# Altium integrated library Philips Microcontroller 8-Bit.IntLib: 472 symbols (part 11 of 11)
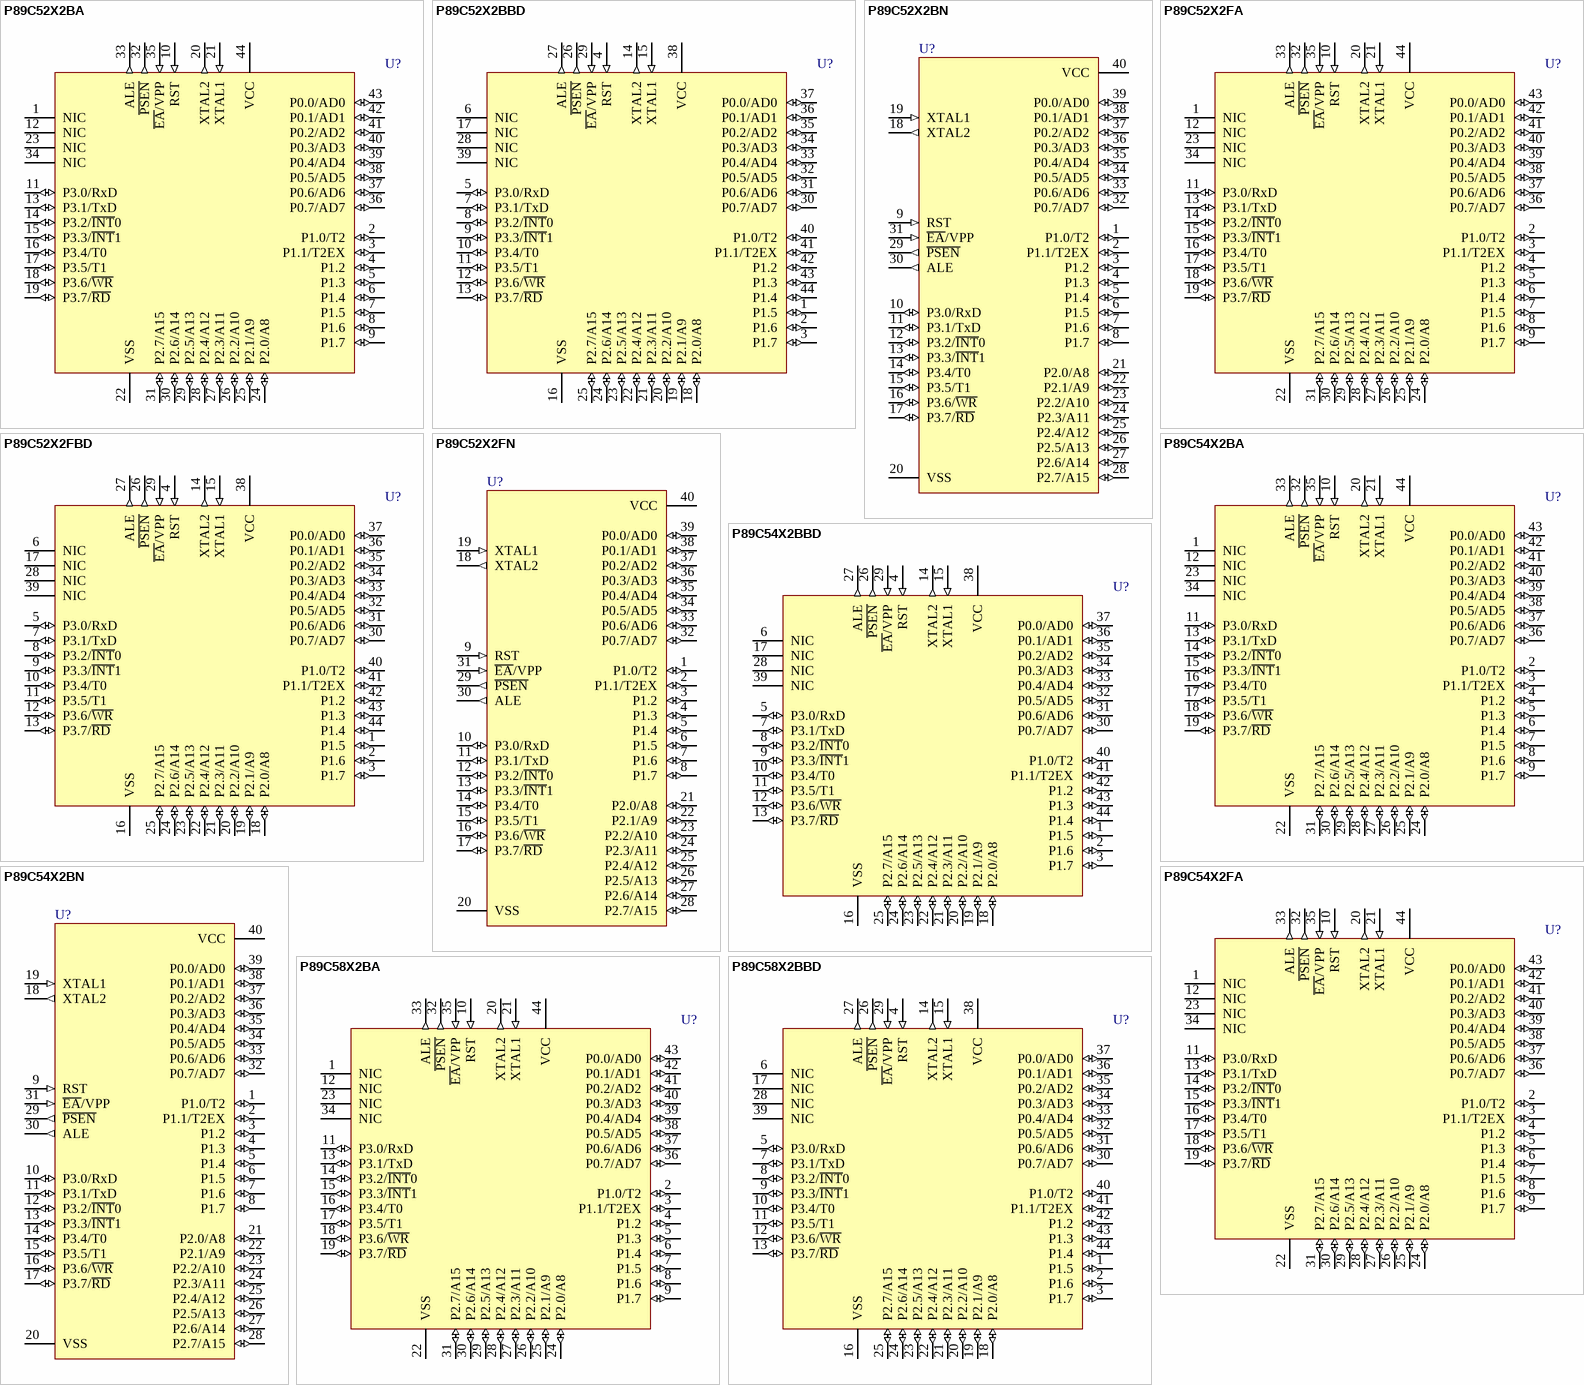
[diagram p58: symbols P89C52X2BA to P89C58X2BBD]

## P89C54X2BBD
designator U?
80C51 8-Bit Flash Microcontroller Family, 16 kB Flash
footprint SOT389-1_N (Thin QFP, 44-Leads, Body 10x10mm, Pitch 0.8mm, IPC Medium Density)
footprint SOT389-1_L (Thin QFP, 44-Leads, Body 10x10mm, Pitch 0.8mm, IPC High Density)
footprint SOT389-1_M (Thin QFP, 44-Leads, Body 10x10mm, Pitch 0.8mm, IPC Low Density)
pins: 1 P1.5 (io), 2 P1.6 (io), 3 P1.7 (io), 4 RST (in), 5 P3.0/RxD (io), 6 NIC, 7 P3.1/TxD (io), 8 P3.2/~{INT}0 (io), 9 P3.3/~{INT}1 (io), 10 P3.4/T0 (io), 11 P3.5/T1 (io), 12 P3.6/~{WR} (io), 13 P3.7/~{RD} (io), 14 XTAL2 (out), 15 XTAL1 (in), 16 VSS (power), 17 NIC, 18 P2.0/A8 (io), 19 P2.1/A9 (io), 20 P2.2/A10 (io), 21 P2.3/A11 (io), 22 P2.4/A12 (io), 23 P2.5/A13 (io), 24 P2.6/A14 (io), 25 P2.7/A15 (io), 26 ~{PSEN} (out), 27 ALE (out), 28 NIC, 29 ~{EA}/VPP (in), 30 P0.7/AD7 (io), 31 P0.6/AD6 (io), 32 P0.5/AD5 (io), 33 P0.4/AD4 (io), 34 P0.3/AD3 (io), 35 P0.2/AD2 (io), 36 P0.1/AD1 (io), 37 P0.0/AD0 (io), 38 VCC (power), 39 NIC, 40 P1.0/T2 (io), 41 P1.1/T2EX (io), 42 P1.2 (io), 43 P1.3 (io), 44 P1.4 (io)

## P89C54X2BN
designator U?
80C51 8-Bit Flash Microcontroller Family, 16 kB Flash
footprint SOT129-1 (DIP, Plastic; 40 Leads; Row Spacing 15.24 mm; Pitch 2.54 mm)
pins: 1 P1.0/T2 (io), 2 P1.1/T2EX (io), 3 P1.2 (io), 4 P1.3 (io), 5 P1.4 (io), 6 P1.5 (io), 7 P1.6 (io), 8 P1.7 (io), 9 RST (in), 10 P3.0/RxD (io), 11 P3.1/TxD (io), 12 P3.2/~{INT}0 (io), 13 P3.3/~{INT}1 (io), 14 P3.4/T0 (io), 15 P3.5/T1 (io), 16 P3.6/~{WR} (io), 17 P3.7/~{RD} (io), 18 XTAL2 (out), 19 XTAL1 (in), 20 VSS (power), 21 P2.0/A8 (io), 22 P2.1/A9 (io), 23 P2.2/A10 (io), 24 P2.3/A11 (io), 25 P2.4/A12 (io), 26 P2.5/A13 (io), 27 P2.6/A14 (io), 28 P2.7/A15 (io), 29 ~{PSEN} (out), 30 ALE (out), 31 ~{EA}/VPP (in), 32 P0.7/AD7 (io), 33 P0.6/AD6 (io), 34 P0.5/AD5 (io), 35 P0.4/AD4 (io), 36 P0.3/AD3 (io), 37 P0.2/AD2 (io), 38 P0.1/AD1 (io), 39 P0.0/AD0 (io), 40 VCC (power)

## P89C54X2FA
designator U?
80C51 8-Bit Flash Microcontroller Family, 16 kB Flash
footprint SOT187-2_N (Leaded Chip Carrier, 44-Leads, Body 16.6x16.6mm, Pitch 1.27mm, IPC Medium Density)
footprint SOT187-2_L (Leaded Chip Carrier, 44-Leads, Body 16.6x16.6mm, Pitch 1.27mm, IPC High Density)
footprint SOT187-2_M (Leaded Chip Carrier, 44-Leads, Body 16.6x16.6mm, Pitch 1.27mm, IPC Low Density)
pins: 1 NIC, 2 P1.0/T2 (io), 3 P1.1/T2EX (io), 4 P1.2 (io), 5 P1.3 (io), 6 P1.4 (io), 7 P1.5 (io), 8 P1.6 (io), 9 P1.7 (io), 10 RST (in), 11 P3.0/RxD (io), 12 NIC, 13 P3.1/TxD (io), 14 P3.2/~{INT}0 (io), 15 P3.3/~{INT}1 (io), 16 P3.4/T0 (io), 17 P3.5/T1 (io), 18 P3.6/~{WR} (io), 19 P3.7/~{RD} (io), 20 XTAL2 (out), 21 XTAL1 (in), 22 VSS (power), 23 NIC, 24 P2.0/A8 (io), 25 P2.1/A9 (io), 26 P2.2/A10 (io), 27 P2.3/A11 (io), 28 P2.4/A12 (io), 29 P2.5/A13 (io), 30 P2.6/A14 (io), 31 P2.7/A15 (io), 32 ~{PSEN} (out), 33 ALE (out), 34 NIC, 35 ~{EA}/VPP (in), 36 P0.7/AD7 (io), 37 P0.6/AD6 (io), 38 P0.5/AD5 (io), 39 P0.4/AD4 (io), 40 P0.3/AD3 (io), 41 P0.2/AD2 (io), 42 P0.1/AD1 (io), 43 P0.0/AD0 (io), 44 VCC (power)

## P89C58X2BA
designator U?
80C51 8-Bit Flash Microcontroller Family, 32 kB Flash
footprint SOT187-2_N (Leaded Chip Carrier, 44-Leads, Body 16.6x16.6mm, Pitch 1.27mm, IPC Medium Density)
footprint SOT187-2_L (Leaded Chip Carrier, 44-Leads, Body 16.6x16.6mm, Pitch 1.27mm, IPC High Density)
footprint SOT187-2_M (Leaded Chip Carrier, 44-Leads, Body 16.6x16.6mm, Pitch 1.27mm, IPC Low Density)
pins: 1 NIC, 2 P1.0/T2 (io), 3 P1.1/T2EX (io), 4 P1.2 (io), 5 P1.3 (io), 6 P1.4 (io), 7 P1.5 (io), 8 P1.6 (io), 9 P1.7 (io), 10 RST (in), 11 P3.0/RxD (io), 12 NIC, 13 P3.1/TxD (io), 14 P3.2/~{INT}0 (io), 15 P3.3/~{INT}1 (io), 16 P3.4/T0 (io), 17 P3.5/T1 (io), 18 P3.6/~{WR} (io), 19 P3.7/~{RD} (io), 20 XTAL2 (out), 21 XTAL1 (in), 22 VSS (power), 23 NIC, 24 P2.0/A8 (io), 25 P2.1/A9 (io), 26 P2.2/A10 (io), 27 P2.3/A11 (io), 28 P2.4/A12 (io), 29 P2.5/A13 (io), 30 P2.6/A14 (io), 31 P2.7/A15 (io), 32 ~{PSEN} (out), 33 ALE (out), 34 NIC, 35 ~{EA}/VPP (in), 36 P0.7/AD7 (io), 37 P0.6/AD6 (io), 38 P0.5/AD5 (io), 39 P0.4/AD4 (io), 40 P0.3/AD3 (io), 41 P0.2/AD2 (io), 42 P0.1/AD1 (io), 43 P0.0/AD0 (io), 44 VCC (power)

## P89C58X2BBD
designator U?
80C51 8-Bit Flash Microcontroller Family, 32 kB Flash
footprint SOT389-1_N (Thin QFP, 44-Leads, Body 10x10mm, Pitch 0.8mm, IPC Medium Density)
footprint SOT389-1_L (Thin QFP, 44-Leads, Body 10x10mm, Pitch 0.8mm, IPC High Density)
footprint SOT389-1_M (Thin QFP, 44-Leads, Body 10x10mm, Pitch 0.8mm, IPC Low Density)
pins: 1 P1.5 (io), 2 P1.6 (io), 3 P1.7 (io), 4 RST (in), 5 P3.0/RxD (io), 6 NIC, 7 P3.1/TxD (io), 8 P3.2/~{INT}0 (io), 9 P3.3/~{INT}1 (io), 10 P3.4/T0 (io), 11 P3.5/T1 (io), 12 P3.6/~{WR} (io), 13 P3.7/~{RD} (io), 14 XTAL2 (out), 15 XTAL1 (in), 16 VSS (power), 17 NIC, 18 P2.0/A8 (io), 19 P2.1/A9 (io), 20 P2.2/A10 (io), 21 P2.3/A11 (io), 22 P2.4/A12 (io), 23 P2.5/A13 (io), 24 P2.6/A14 (io), 25 P2.7/A15 (io), 26 ~{PSEN} (out), 27 ALE (out), 28 NIC, 29 ~{EA}/VPP (in), 30 P0.7/AD7 (io), 31 P0.6/AD6 (io), 32 P0.5/AD5 (io), 33 P0.4/AD4 (io), 34 P0.3/AD3 (io), 35 P0.2/AD2 (io), 36 P0.1/AD1 (io), 37 P0.0/AD0 (io), 38 VCC (power), 39 NIC, 40 P1.0/T2 (io), 41 P1.1/T2EX (io), 42 P1.2 (io), 43 P1.3 (io), 44 P1.4 (io)

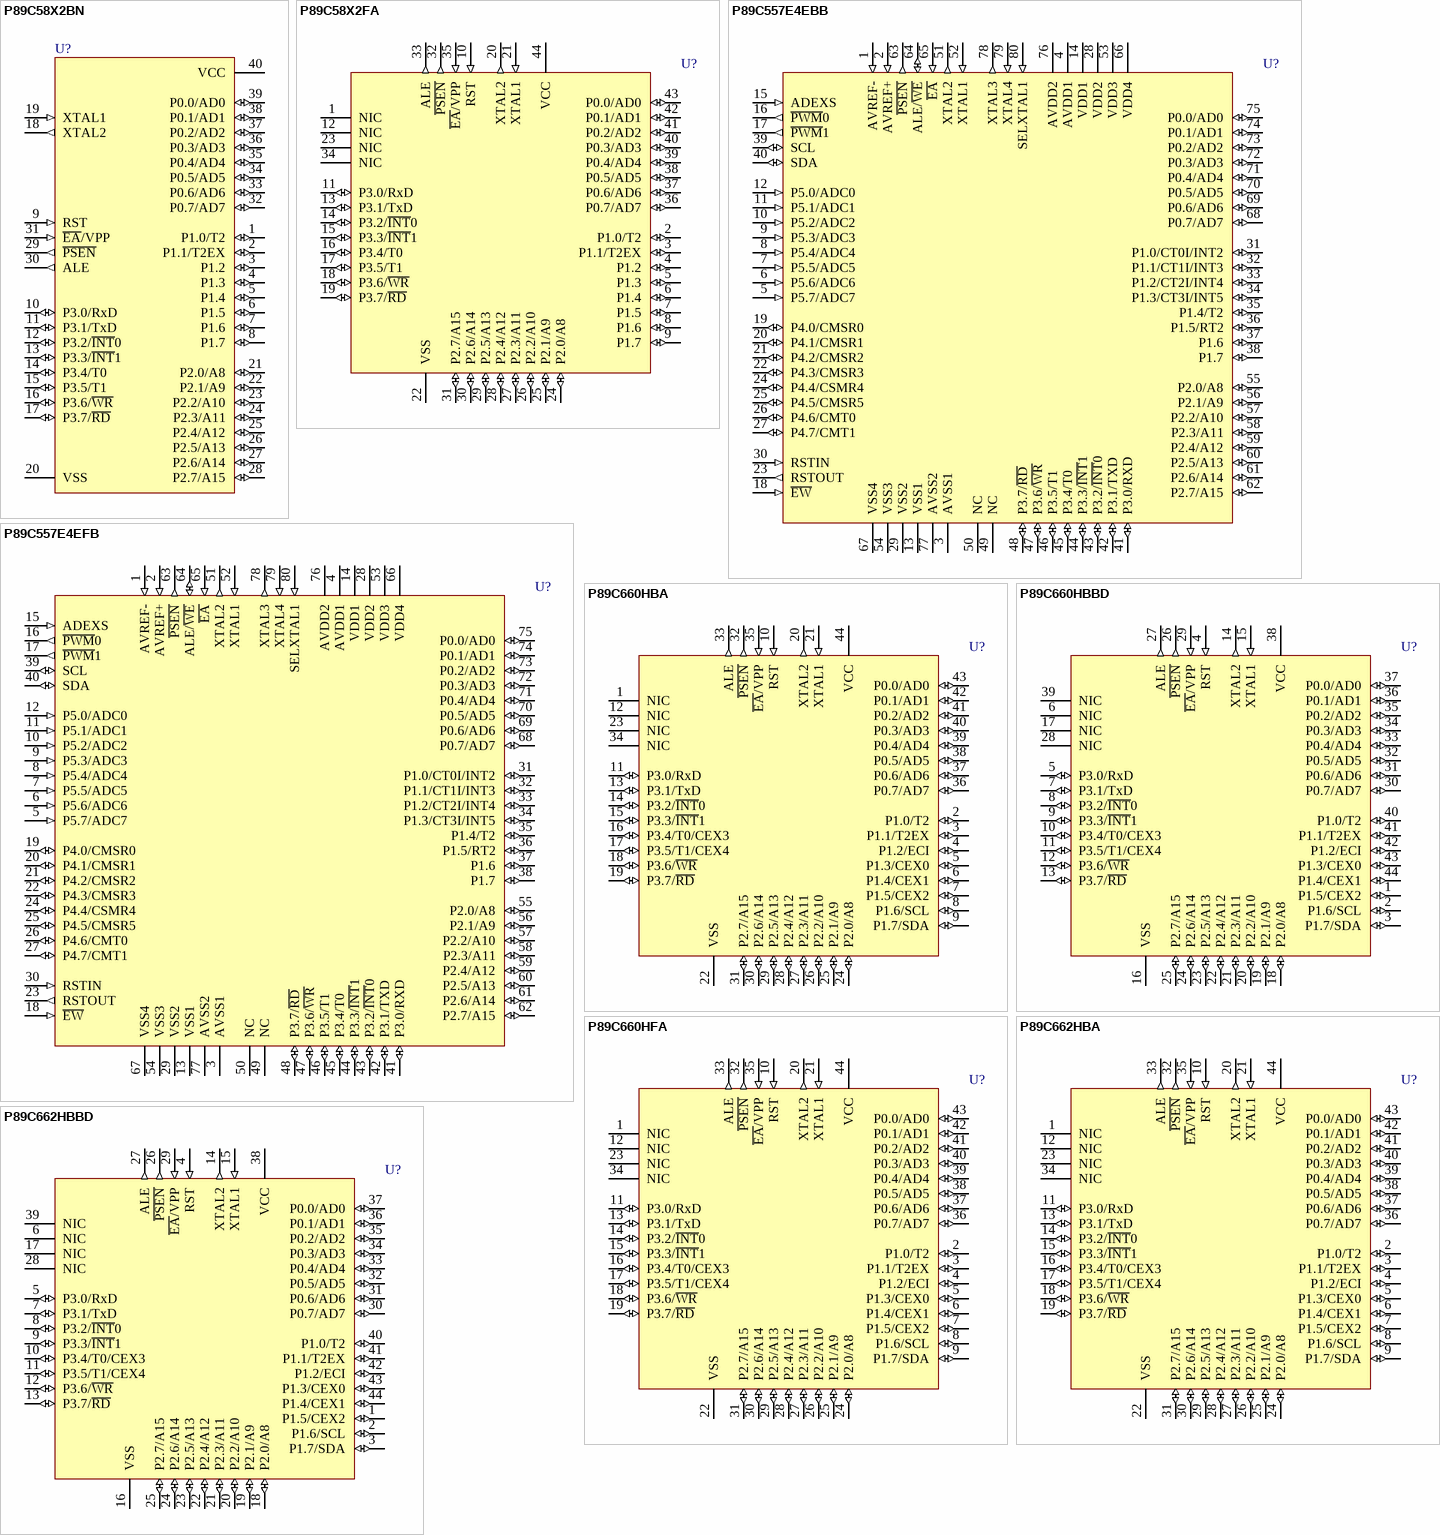
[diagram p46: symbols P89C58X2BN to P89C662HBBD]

## P89C58X2BN
designator U?
80C51 8-Bit Flash Microcontroller Family, 32 kB Flash
footprint SOT129-1 (DIP, Plastic; 40 Leads; Row Spacing 15.24 mm; Pitch 2.54 mm)
pins: 1 P1.0/T2 (io), 2 P1.1/T2EX (io), 3 P1.2 (io), 4 P1.3 (io), 5 P1.4 (io), 6 P1.5 (io), 7 P1.6 (io), 8 P1.7 (io), 9 RST (in), 10 P3.0/RxD (io), 11 P3.1/TxD (io), 12 P3.2/~{INT}0 (io), 13 P3.3/~{INT}1 (io), 14 P3.4/T0 (io), 15 P3.5/T1 (io), 16 P3.6/~{WR} (io), 17 P3.7/~{RD} (io), 18 XTAL2 (out), 19 XTAL1 (in), 20 VSS (power), 21 P2.0/A8 (io), 22 P2.1/A9 (io), 23 P2.2/A10 (io), 24 P2.3/A11 (io), 25 P2.4/A12 (io), 26 P2.5/A13 (io), 27 P2.6/A14 (io), 28 P2.7/A15 (io), 29 ~{PSEN} (out), 30 ALE (out), 31 ~{EA}/VPP (in), 32 P0.7/AD7 (io), 33 P0.6/AD6 (io), 34 P0.5/AD5 (io), 35 P0.4/AD4 (io), 36 P0.3/AD3 (io), 37 P0.2/AD2 (io), 38 P0.1/AD1 (io), 39 P0.0/AD0 (io), 40 VCC (power)

## P89C58X2FA
designator U?
80C51 8-Bit Flash Microcontroller Family, 32 kB Flash
footprint SOT187-2_N (Leaded Chip Carrier, 44-Leads, Body 16.6x16.6mm, Pitch 1.27mm, IPC Medium Density)
footprint SOT187-2_L (Leaded Chip Carrier, 44-Leads, Body 16.6x16.6mm, Pitch 1.27mm, IPC High Density)
footprint SOT187-2_M (Leaded Chip Carrier, 44-Leads, Body 16.6x16.6mm, Pitch 1.27mm, IPC Low Density)
pins: 1 NIC, 2 P1.0/T2 (io), 3 P1.1/T2EX (io), 4 P1.2 (io), 5 P1.3 (io), 6 P1.4 (io), 7 P1.5 (io), 8 P1.6 (io), 9 P1.7 (io), 10 RST (in), 11 P3.0/RxD (io), 12 NIC, 13 P3.1/TxD (io), 14 P3.2/~{INT}0 (io), 15 P3.3/~{INT}1 (io), 16 P3.4/T0 (io), 17 P3.5/T1 (io), 18 P3.6/~{WR} (io), 19 P3.7/~{RD} (io), 20 XTAL2 (out), 21 XTAL1 (in), 22 VSS (power), 23 NIC, 24 P2.0/A8 (io), 25 P2.1/A9 (io), 26 P2.2/A10 (io), 27 P2.3/A11 (io), 28 P2.4/A12 (io), 29 P2.5/A13 (io), 30 P2.6/A14 (io), 31 P2.7/A15 (io), 32 ~{PSEN} (out), 33 ALE (out), 34 NIC, 35 ~{EA}/VPP (in), 36 P0.7/AD7 (io), 37 P0.6/AD6 (io), 38 P0.5/AD5 (io), 39 P0.4/AD4 (io), 40 P0.3/AD3 (io), 41 P0.2/AD2 (io), 42 P0.1/AD1 (io), 43 P0.0/AD0 (io), 44 VCC (power)

## P89C557E4EBB
designator U?
Single-Chip 8-Bit Microcontroller, FEEPROM Type
footprint SOT318-1_N (QFP, 80-Leads, Body 20x14mm, Pitch 0.8mm, IPC Medium Density)
footprint SOT318-1_L (QFP, 80-Leads, Body 20x14mm, Pitch 0.8mm, IPC High Density)
footprint SOT318-1_M (QFP, 80-Leads, Body 20x14mm, Pitch 0.8mm, IPC Low Density)
pins: 1 AVREF- (in), 2 AVREF+ (in), 3 AVSS1 (power), 4 AVDD1 (power), 5 P5.7/ADC7 (in), 6 P5.6/ADC6 (in), 7 P5.5/ADC5 (in), 8 P5.4/ADC4 (in), 9 P5.3/ADC3 (in), 10 P5.2/ADC2 (in), 11 P5.1/ADC1 (in), 12 P5.0/ADC0 (in), 13 VSS1 (power), 14 VDD1 (power), 15 ADEXS (in), 16 ~{PWM}0 (out), 17 ~{PWM}1 (out), 18 ~{EW} (in), 19 P4.0/CMSR0 (io), 20 P4.1/CMSR1 (io), 21 P4.2/CMSR2 (io), 22 P4.3/CMSR3 (io), 23 RSTOUT (out), 24 P4.4/CSMR4 (io), 25 P4.5/CMSR5 (io), 26 P4.6/CMT0 (io), 27 P4.7/CMT1 (io), 28 VDD2 (power), 29 VSS2 (power), 30 RSTIN (in), 31 P1.0/CT0I/INT2 (io), 32 P1.1/CT1I/INT3 (io), 33 P1.2/CT2I/INT4 (io), 34 P1.3/CT3I/INT5 (io), 35 P1.4/T2 (io), 36 P1.5/RT2 (io), 37 P1.6 (io), 38 P1.7 (io), 39 SCL (io), 40 SDA (io), 41 P3.0/RXD (io), 42 P3.1/TXD (io), 43 P3.2/~{INT}0 (io), 44 P3.3/~{INT}1 (io), 45 P3.4/T0 (io), 46 P3.5/T1 (io), 47 P3.6/~{WR} (io), 48 P3.7/~{RD} (io), 49 NC, 50 NC, 51 XTAL2 (out), 52 XTAL1 (in), 53 VDD3 (power), 54 VSS3 (power), 55 P2.0/A8 (io), 56 P2.1/A9 (io), 57 P2.2/A10 (io), 58 P2.3/A11 (io), 59 P2.4/A12 (io), 60 P2.5/A13 (io), 61 P2.6/A14 (io), 62 P2.7/A15 (io), 63 ~{PSEN} (out), 64 ALE/~{WE} (io), 65 ~{EA} (in), 66 VDD4 (power), 67 VSS4 (power), 68 P0.7/AD7 (io), 69 P0.6/AD6 (io), 70 P0.5/AD5 (io), 71 P0.4/AD4 (io), 72 P0.3/AD3 (io), 73 P0.2/AD2 (io), 74 P0.1/AD1 (io), 75 P0.0/AD0 (io), 76 AVDD2 (power), 77 AVSS2 (power), 78 XTAL3 (out), 79 XTAL4 (in), 80 SELXTAL1 (in)

## P89C557E4EFB
designator U?
Single-Chip 8-Bit Microcontroller, FEEPROM Type
footprint SOT318-1_N (QFP, 80-Leads, Body 20x14mm, Pitch 0.8mm, IPC Medium Density)
footprint SOT318-1_L (QFP, 80-Leads, Body 20x14mm, Pitch 0.8mm, IPC High Density)
footprint SOT318-1_M (QFP, 80-Leads, Body 20x14mm, Pitch 0.8mm, IPC Low Density)
pins: 1 AVREF- (in), 2 AVREF+ (in), 3 AVSS1 (power), 4 AVDD1 (power), 5 P5.7/ADC7 (in), 6 P5.6/ADC6 (in), 7 P5.5/ADC5 (in), 8 P5.4/ADC4 (in), 9 P5.3/ADC3 (in), 10 P5.2/ADC2 (in), 11 P5.1/ADC1 (in), 12 P5.0/ADC0 (in), 13 VSS1 (power), 14 VDD1 (power), 15 ADEXS (in), 16 ~{PWM}0 (out), 17 ~{PWM}1 (out), 18 ~{EW} (in), 19 P4.0/CMSR0 (io), 20 P4.1/CMSR1 (io), 21 P4.2/CMSR2 (io), 22 P4.3/CMSR3 (io), 23 RSTOUT (out), 24 P4.4/CSMR4 (io), 25 P4.5/CMSR5 (io), 26 P4.6/CMT0 (io), 27 P4.7/CMT1 (io), 28 VDD2 (power), 29 VSS2 (power), 30 RSTIN (in), 31 P1.0/CT0I/INT2 (io), 32 P1.1/CT1I/INT3 (io), 33 P1.2/CT2I/INT4 (io), 34 P1.3/CT3I/INT5 (io), 35 P1.4/T2 (io), 36 P1.5/RT2 (io), 37 P1.6 (io), 38 P1.7 (io), 39 SCL (io), 40 SDA (io), 41 P3.0/RXD (io), 42 P3.1/TXD (io), 43 P3.2/~{INT}0 (io), 44 P3.3/~{INT}1 (io), 45 P3.4/T0 (io), 46 P3.5/T1 (io), 47 P3.6/~{WR} (io), 48 P3.7/~{RD} (io), 49 NC, 50 NC, 51 XTAL2 (out), 52 XTAL1 (in), 53 VDD3 (power), 54 VSS3 (power), 55 P2.0/A8 (io), 56 P2.1/A9 (io), 57 P2.2/A10 (io), 58 P2.3/A11 (io), 59 P2.4/A12 (io), 60 P2.5/A13 (io), 61 P2.6/A14 (io), 62 P2.7/A15 (io), 63 ~{PSEN} (out), 64 ALE/~{WE} (io), 65 ~{EA} (in), 66 VDD4 (power), 67 VSS4 (power), 68 P0.7/AD7 (io), 69 P0.6/AD6 (io), 70 P0.5/AD5 (io), 71 P0.4/AD4 (io), 72 P0.3/AD3 (io), 73 P0.2/AD2 (io), 74 P0.1/AD1 (io), 75 P0.0/AD0 (io), 76 AVDD2 (power), 77 AVSS2 (power), 78 XTAL3 (out), 79 XTAL4 (in), 80 SELXTAL1 (in)

## P89C660HBA
designator U?
80C51 8-Bit Flash Microcontroller Family, 16 kB ISP/IAP Flash with 512 B RAM
footprint SOT187-2_N (Leaded Chip Carrier, 44-Leads, Body 16.6x16.6mm, Pitch 1.27mm, IPC Medium Density)
footprint SOT187-2_L (Leaded Chip Carrier, 44-Leads, Body 16.6x16.6mm, Pitch 1.27mm, IPC High Density)
footprint SOT187-2_M (Leaded Chip Carrier, 44-Leads, Body 16.6x16.6mm, Pitch 1.27mm, IPC Low Density)
pins: 1 NIC, 2 P1.0/T2 (io), 3 P1.1/T2EX (io), 4 P1.2/ECI (io), 5 P1.3/CEX0 (io), 6 P1.4/CEX1 (io), 7 P1.5/CEX2 (io), 8 P1.6/SCL (io), 9 P1.7/SDA (io), 10 RST (in), 11 P3.0/RxD (io), 12 NIC, 13 P3.1/TxD (io), 14 P3.2/~{INT}0 (io), 15 P3.3/~{INT}1 (io), 16 P3.4/T0/CEX3 (io), 17 P3.5/T1/CEX4 (io), 18 P3.6/~{WR} (io), 19 P3.7/~{RD} (io), 20 XTAL2 (out), 21 XTAL1 (in), 22 VSS (power), 23 NIC, 24 P2.0/A8 (io), 25 P2.1/A9 (io), 26 P2.2/A10 (io), 27 P2.3/A11 (io), 28 P2.4/A12 (io), 29 P2.5/A13 (io), 30 P2.6/A14 (io), 31 P2.7/A15 (io), 32 ~{PSEN} (out), 33 ALE (out), 34 NIC, 35 ~{EA}/VPP (in), 36 P0.7/AD7 (io), 37 P0.6/AD6 (io), 38 P0.5/AD5 (io), 39 P0.4/AD4 (io), 40 P0.3/AD3 (io), 41 P0.2/AD2 (io), 42 P0.1/AD1 (io), 43 P0.0/AD0 (io), 44 VCC (power)

## P89C660HBBD
designator U?
80C51 8-Bit Flash Microcontroller Family, 16 kB ISP/IAP Flash with 512 B RAM
footprint SOT389-1_N (Thin QFP, 44-Leads, Body 10x10mm, Pitch 0.8mm, IPC Medium Density)
footprint SOT389-1_L (Thin QFP, 44-Leads, Body 10x10mm, Pitch 0.8mm, IPC High Density)
footprint SOT389-1_M (Thin QFP, 44-Leads, Body 10x10mm, Pitch 0.8mm, IPC Low Density)
pins: 1 P1.5/CEX2 (io), 2 P1.6/SCL (io), 3 P1.7/SDA (io), 4 RST (in), 5 P3.0/RxD (io), 6 NIC, 7 P3.1/TxD (io), 8 P3.2/~{INT}0 (io), 9 P3.3/~{INT}1 (io), 10 P3.4/T0/CEX3 (io), 11 P3.5/T1/CEX4 (io), 12 P3.6/~{WR} (io), 13 P3.7/~{RD} (io), 14 XTAL2 (out), 15 XTAL1 (in), 16 VSS (power), 17 NIC, 18 P2.0/A8 (io), 19 P2.1/A9 (io), 20 P2.2/A10 (io), 21 P2.3/A11 (io), 22 P2.4/A12 (io), 23 P2.5/A13 (io), 24 P2.6/A14 (io), 25 P2.7/A15 (io), 26 ~{PSEN} (out), 27 ALE (out), 28 NIC, 29 ~{EA}/VPP (in), 30 P0.7/AD7 (io), 31 P0.6/AD6 (io), 32 P0.5/AD5 (io), 33 P0.4/AD4 (io), 34 P0.3/AD3 (io), 35 P0.2/AD2 (io), 36 P0.1/AD1 (io), 37 P0.0/AD0 (io), 38 VCC (power), 39 NIC, 40 P1.0/T2 (io), 41 P1.1/T2EX (io), 42 P1.2/ECI (io), 43 P1.3/CEX0 (io), 44 P1.4/CEX1 (io)

## P89C660HFA
designator U?
80C51 8-Bit Flash Microcontroller Family, 16 kB ISP/IAP Flash with 512 B RAM
footprint SOT187-2_N (Leaded Chip Carrier, 44-Leads, Body 16.6x16.6mm, Pitch 1.27mm, IPC Medium Density)
footprint SOT187-2_L (Leaded Chip Carrier, 44-Leads, Body 16.6x16.6mm, Pitch 1.27mm, IPC High Density)
footprint SOT187-2_M (Leaded Chip Carrier, 44-Leads, Body 16.6x16.6mm, Pitch 1.27mm, IPC Low Density)
pins: 1 NIC, 2 P1.0/T2 (io), 3 P1.1/T2EX (io), 4 P1.2/ECI (io), 5 P1.3/CEX0 (io), 6 P1.4/CEX1 (io), 7 P1.5/CEX2 (io), 8 P1.6/SCL (io), 9 P1.7/SDA (io), 10 RST (in), 11 P3.0/RxD (io), 12 NIC, 13 P3.1/TxD (io), 14 P3.2/~{INT}0 (io), 15 P3.3/~{INT}1 (io), 16 P3.4/T0/CEX3 (io), 17 P3.5/T1/CEX4 (io), 18 P3.6/~{WR} (io), 19 P3.7/~{RD} (io), 20 XTAL2 (out), 21 XTAL1 (in), 22 VSS (power), 23 NIC, 24 P2.0/A8 (io), 25 P2.1/A9 (io), 26 P2.2/A10 (io), 27 P2.3/A11 (io), 28 P2.4/A12 (io), 29 P2.5/A13 (io), 30 P2.6/A14 (io), 31 P2.7/A15 (io), 32 ~{PSEN} (out), 33 ALE (out), 34 NIC, 35 ~{EA}/VPP (in), 36 P0.7/AD7 (io), 37 P0.6/AD6 (io), 38 P0.5/AD5 (io), 39 P0.4/AD4 (io), 40 P0.3/AD3 (io), 41 P0.2/AD2 (io), 42 P0.1/AD1 (io), 43 P0.0/AD0 (io), 44 VCC (power)

## P89C662HBA
designator U?
80C51 8-Bit Flash Microcontroller Family, 32 kB ISP/IAP Flash with 1 kB RAM
footprint SOT187-2_N (Leaded Chip Carrier, 44-Leads, Body 16.6x16.6mm, Pitch 1.27mm, IPC Medium Density)
footprint SOT187-2_L (Leaded Chip Carrier, 44-Leads, Body 16.6x16.6mm, Pitch 1.27mm, IPC High Density)
footprint SOT187-2_M (Leaded Chip Carrier, 44-Leads, Body 16.6x16.6mm, Pitch 1.27mm, IPC Low Density)
pins: 1 NIC, 2 P1.0/T2 (io), 3 P1.1/T2EX (io), 4 P1.2/ECI (io), 5 P1.3/CEX0 (io), 6 P1.4/CEX1 (io), 7 P1.5/CEX2 (io), 8 P1.6/SCL (io), 9 P1.7/SDA (io), 10 RST (in), 11 P3.0/RxD (io), 12 NIC, 13 P3.1/TxD (io), 14 P3.2/~{INT}0 (io), 15 P3.3/~{INT}1 (io), 16 P3.4/T0/CEX3 (io), 17 P3.5/T1/CEX4 (io), 18 P3.6/~{WR} (io), 19 P3.7/~{RD} (io), 20 XTAL2 (out), 21 XTAL1 (in), 22 VSS (power), 23 NIC, 24 P2.0/A8 (io), 25 P2.1/A9 (io), 26 P2.2/A10 (io), 27 P2.3/A11 (io), 28 P2.4/A12 (io), 29 P2.5/A13 (io), 30 P2.6/A14 (io), 31 P2.7/A15 (io), 32 ~{PSEN} (out), 33 ALE (out), 34 NIC, 35 ~{EA}/VPP (in), 36 P0.7/AD7 (io), 37 P0.6/AD6 (io), 38 P0.5/AD5 (io), 39 P0.4/AD4 (io), 40 P0.3/AD3 (io), 41 P0.2/AD2 (io), 42 P0.1/AD1 (io), 43 P0.0/AD0 (io), 44 VCC (power)

## P89C662HBBD
designator U?
80C51 8-Bit Flash Microcontroller Family, 32 kB ISP/IAP Flash with 1 kB RAM
footprint SOT389-1_N (Thin QFP, 44-Leads, Body 10x10mm, Pitch 0.8mm, IPC Medium Density)
footprint SOT389-1_L (Thin QFP, 44-Leads, Body 10x10mm, Pitch 0.8mm, IPC High Density)
footprint SOT389-1_M (Thin QFP, 44-Leads, Body 10x10mm, Pitch 0.8mm, IPC Low Density)
pins: 1 P1.5/CEX2 (io), 2 P1.6/SCL (io), 3 P1.7/SDA (io), 4 RST (in), 5 P3.0/RxD (io), 6 NIC, 7 P3.1/TxD (io), 8 P3.2/~{INT}0 (io), 9 P3.3/~{INT}1 (io), 10 P3.4/T0/CEX3 (io), 11 P3.5/T1/CEX4 (io), 12 P3.6/~{WR} (io), 13 P3.7/~{RD} (io), 14 XTAL2 (out), 15 XTAL1 (in), 16 VSS (power), 17 NIC, 18 P2.0/A8 (io), 19 P2.1/A9 (io), 20 P2.2/A10 (io), 21 P2.3/A11 (io), 22 P2.4/A12 (io), 23 P2.5/A13 (io), 24 P2.6/A14 (io), 25 P2.7/A15 (io), 26 ~{PSEN} (out), 27 ALE (out), 28 NIC, 29 ~{EA}/VPP (in), 30 P0.7/AD7 (io), 31 P0.6/AD6 (io), 32 P0.5/AD5 (io), 33 P0.4/AD4 (io), 34 P0.3/AD3 (io), 35 P0.2/AD2 (io), 36 P0.1/AD1 (io), 37 P0.0/AD0 (io), 38 VCC (power), 39 NIC, 40 P1.0/T2 (io), 41 P1.1/T2EX (io), 42 P1.2/ECI (io), 43 P1.3/CEX0 (io), 44 P1.4/CEX1 (io)

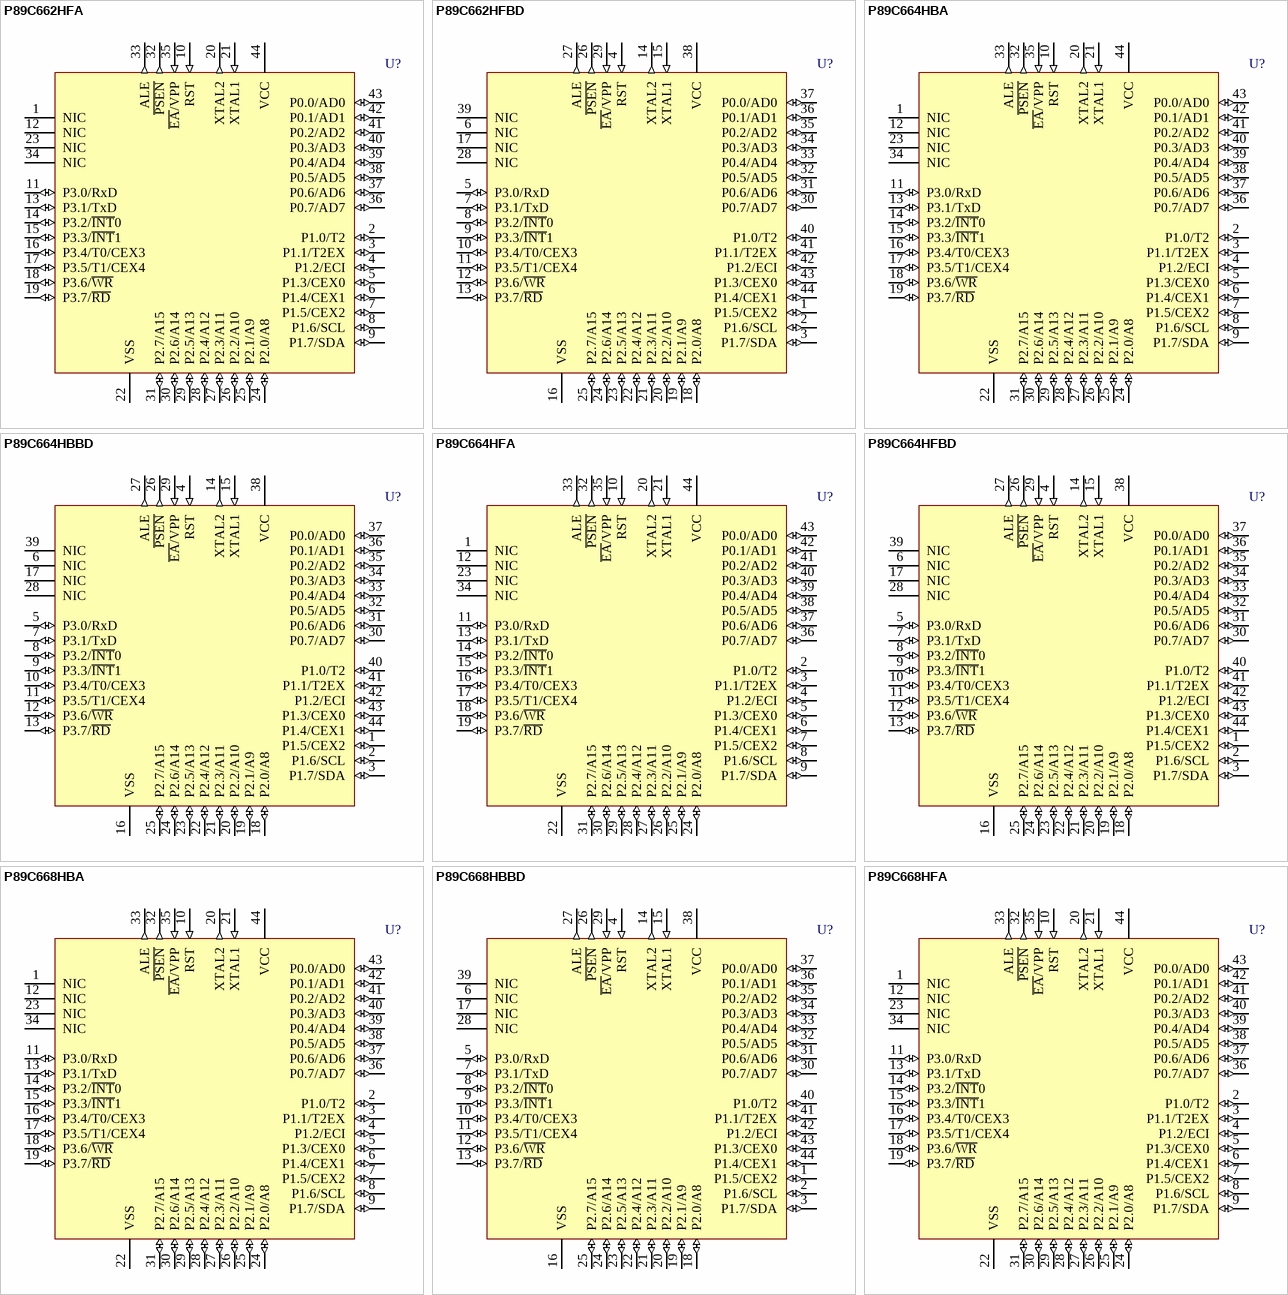
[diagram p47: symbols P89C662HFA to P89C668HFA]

## P89C662HFA
designator U?
80C51 8-Bit Flash Microcontroller Family, 32 kB ISP/IAP Flash with 1 kB RAM
footprint SOT187-2_N (Leaded Chip Carrier, 44-Leads, Body 16.6x16.6mm, Pitch 1.27mm, IPC Medium Density)
footprint SOT187-2_L (Leaded Chip Carrier, 44-Leads, Body 16.6x16.6mm, Pitch 1.27mm, IPC High Density)
footprint SOT187-2_M (Leaded Chip Carrier, 44-Leads, Body 16.6x16.6mm, Pitch 1.27mm, IPC Low Density)
pins: 1 NIC, 2 P1.0/T2 (io), 3 P1.1/T2EX (io), 4 P1.2/ECI (io), 5 P1.3/CEX0 (io), 6 P1.4/CEX1 (io), 7 P1.5/CEX2 (io), 8 P1.6/SCL (io), 9 P1.7/SDA (io), 10 RST (in), 11 P3.0/RxD (io), 12 NIC, 13 P3.1/TxD (io), 14 P3.2/~{INT}0 (io), 15 P3.3/~{INT}1 (io), 16 P3.4/T0/CEX3 (io), 17 P3.5/T1/CEX4 (io), 18 P3.6/~{WR} (io), 19 P3.7/~{RD} (io), 20 XTAL2 (out), 21 XTAL1 (in), 22 VSS (power), 23 NIC, 24 P2.0/A8 (io), 25 P2.1/A9 (io), 26 P2.2/A10 (io), 27 P2.3/A11 (io), 28 P2.4/A12 (io), 29 P2.5/A13 (io), 30 P2.6/A14 (io), 31 P2.7/A15 (io), 32 ~{PSEN} (out), 33 ALE (out), 34 NIC, 35 ~{EA}/VPP (in), 36 P0.7/AD7 (io), 37 P0.6/AD6 (io), 38 P0.5/AD5 (io), 39 P0.4/AD4 (io), 40 P0.3/AD3 (io), 41 P0.2/AD2 (io), 42 P0.1/AD1 (io), 43 P0.0/AD0 (io), 44 VCC (power)

## P89C662HFBD
designator U?
80C51 8-Bit Flash Microcontroller Family, 32 kB ISP/IAP Flash with 1 kB RAM
footprint SOT389-1_N (Thin QFP, 44-Leads, Body 10x10mm, Pitch 0.8mm, IPC Medium Density)
footprint SOT389-1_L (Thin QFP, 44-Leads, Body 10x10mm, Pitch 0.8mm, IPC High Density)
footprint SOT389-1_M (Thin QFP, 44-Leads, Body 10x10mm, Pitch 0.8mm, IPC Low Density)
pins: 1 P1.5/CEX2 (io), 2 P1.6/SCL (io), 3 P1.7/SDA (io), 4 RST (in), 5 P3.0/RxD (io), 6 NIC, 7 P3.1/TxD (io), 8 P3.2/~{INT}0 (io), 9 P3.3/~{INT}1 (io), 10 P3.4/T0/CEX3 (io), 11 P3.5/T1/CEX4 (io), 12 P3.6/~{WR} (io), 13 P3.7/~{RD} (io), 14 XTAL2 (out), 15 XTAL1 (in), 16 VSS (power), 17 NIC, 18 P2.0/A8 (io), 19 P2.1/A9 (io), 20 P2.2/A10 (io), 21 P2.3/A11 (io), 22 P2.4/A12 (io), 23 P2.5/A13 (io), 24 P2.6/A14 (io), 25 P2.7/A15 (io), 26 ~{PSEN} (out), 27 ALE (out), 28 NIC, 29 ~{EA}/VPP (in), 30 P0.7/AD7 (io), 31 P0.6/AD6 (io), 32 P0.5/AD5 (io), 33 P0.4/AD4 (io), 34 P0.3/AD3 (io), 35 P0.2/AD2 (io), 36 P0.1/AD1 (io), 37 P0.0/AD0 (io), 38 VCC (power), 39 NIC, 40 P1.0/T2 (io), 41 P1.1/T2EX (io), 42 P1.2/ECI (io), 43 P1.3/CEX0 (io), 44 P1.4/CEX1 (io)

## P89C664HBA
designator U?
80C51 8-Bit Flash Microcontroller Family, 64 kB ISP/IAP Flash with 2 kB RAM
footprint SOT187-2_N (Leaded Chip Carrier, 44-Leads, Body 16.6x16.6mm, Pitch 1.27mm, IPC Medium Density)
footprint SOT187-2_L (Leaded Chip Carrier, 44-Leads, Body 16.6x16.6mm, Pitch 1.27mm, IPC High Density)
footprint SOT187-2_M (Leaded Chip Carrier, 44-Leads, Body 16.6x16.6mm, Pitch 1.27mm, IPC Low Density)
pins: 1 NIC, 2 P1.0/T2 (io), 3 P1.1/T2EX (io), 4 P1.2/ECI (io), 5 P1.3/CEX0 (io), 6 P1.4/CEX1 (io), 7 P1.5/CEX2 (io), 8 P1.6/SCL (io), 9 P1.7/SDA (io), 10 RST (in), 11 P3.0/RxD (io), 12 NIC, 13 P3.1/TxD (io), 14 P3.2/~{INT}0 (io), 15 P3.3/~{INT}1 (io), 16 P3.4/T0/CEX3 (io), 17 P3.5/T1/CEX4 (io), 18 P3.6/~{WR} (io), 19 P3.7/~{RD} (io), 20 XTAL2 (out), 21 XTAL1 (in), 22 VSS (power), 23 NIC, 24 P2.0/A8 (io), 25 P2.1/A9 (io), 26 P2.2/A10 (io), 27 P2.3/A11 (io), 28 P2.4/A12 (io), 29 P2.5/A13 (io), 30 P2.6/A14 (io), 31 P2.7/A15 (io), 32 ~{PSEN} (out), 33 ALE (out), 34 NIC, 35 ~{EA}/VPP (in), 36 P0.7/AD7 (io), 37 P0.6/AD6 (io), 38 P0.5/AD5 (io), 39 P0.4/AD4 (io), 40 P0.3/AD3 (io), 41 P0.2/AD2 (io), 42 P0.1/AD1 (io), 43 P0.0/AD0 (io), 44 VCC (power)

## P89C664HBBD
designator U?
80C51 8-Bit Flash Microcontroller Family, 64 kB ISP/IAP Flash with 2 kB RAM
footprint SOT389-1_N (Thin QFP, 44-Leads, Body 10x10mm, Pitch 0.8mm, IPC Medium Density)
footprint SOT389-1_L (Thin QFP, 44-Leads, Body 10x10mm, Pitch 0.8mm, IPC High Density)
footprint SOT389-1_M (Thin QFP, 44-Leads, Body 10x10mm, Pitch 0.8mm, IPC Low Density)
pins: 1 P1.5/CEX2 (io), 2 P1.6/SCL (io), 3 P1.7/SDA (io), 4 RST (in), 5 P3.0/RxD (io), 6 NIC, 7 P3.1/TxD (io), 8 P3.2/~{INT}0 (io), 9 P3.3/~{INT}1 (io), 10 P3.4/T0/CEX3 (io), 11 P3.5/T1/CEX4 (io), 12 P3.6/~{WR} (io), 13 P3.7/~{RD} (io), 14 XTAL2 (out), 15 XTAL1 (in), 16 VSS (power), 17 NIC, 18 P2.0/A8 (io), 19 P2.1/A9 (io), 20 P2.2/A10 (io), 21 P2.3/A11 (io), 22 P2.4/A12 (io), 23 P2.5/A13 (io), 24 P2.6/A14 (io), 25 P2.7/A15 (io), 26 ~{PSEN} (out), 27 ALE (out), 28 NIC, 29 ~{EA}/VPP (in), 30 P0.7/AD7 (io), 31 P0.6/AD6 (io), 32 P0.5/AD5 (io), 33 P0.4/AD4 (io), 34 P0.3/AD3 (io), 35 P0.2/AD2 (io), 36 P0.1/AD1 (io), 37 P0.0/AD0 (io), 38 VCC (power), 39 NIC, 40 P1.0/T2 (io), 41 P1.1/T2EX (io), 42 P1.2/ECI (io), 43 P1.3/CEX0 (io), 44 P1.4/CEX1 (io)

## P89C664HFA
designator U?
80C51 8-Bit Flash Microcontroller Family, 64 kB ISP/IAP Flash with 2 kB RAM
footprint SOT187-2_N (Leaded Chip Carrier, 44-Leads, Body 16.6x16.6mm, Pitch 1.27mm, IPC Medium Density)
footprint SOT187-2_L (Leaded Chip Carrier, 44-Leads, Body 16.6x16.6mm, Pitch 1.27mm, IPC High Density)
footprint SOT187-2_M (Leaded Chip Carrier, 44-Leads, Body 16.6x16.6mm, Pitch 1.27mm, IPC Low Density)
pins: 1 NIC, 2 P1.0/T2 (io), 3 P1.1/T2EX (io), 4 P1.2/ECI (io), 5 P1.3/CEX0 (io), 6 P1.4/CEX1 (io), 7 P1.5/CEX2 (io), 8 P1.6/SCL (io), 9 P1.7/SDA (io), 10 RST (in), 11 P3.0/RxD (io), 12 NIC, 13 P3.1/TxD (io), 14 P3.2/~{INT}0 (io), 15 P3.3/~{INT}1 (io), 16 P3.4/T0/CEX3 (io), 17 P3.5/T1/CEX4 (io), 18 P3.6/~{WR} (io), 19 P3.7/~{RD} (io), 20 XTAL2 (out), 21 XTAL1 (in), 22 VSS (power), 23 NIC, 24 P2.0/A8 (io), 25 P2.1/A9 (io), 26 P2.2/A10 (io), 27 P2.3/A11 (io), 28 P2.4/A12 (io), 29 P2.5/A13 (io), 30 P2.6/A14 (io), 31 P2.7/A15 (io), 32 ~{PSEN} (out), 33 ALE (out), 34 NIC, 35 ~{EA}/VPP (in), 36 P0.7/AD7 (io), 37 P0.6/AD6 (io), 38 P0.5/AD5 (io), 39 P0.4/AD4 (io), 40 P0.3/AD3 (io), 41 P0.2/AD2 (io), 42 P0.1/AD1 (io), 43 P0.0/AD0 (io), 44 VCC (power)

## P89C664HFBD
designator U?
80C51 8-Bit Flash Microcontroller Family, 64 kB ISP/IAP Flash with 2 kB RAM
footprint SOT389-1_N (Thin QFP, 44-Leads, Body 10x10mm, Pitch 0.8mm, IPC Medium Density)
footprint SOT389-1_L (Thin QFP, 44-Leads, Body 10x10mm, Pitch 0.8mm, IPC High Density)
footprint SOT389-1_M (Thin QFP, 44-Leads, Body 10x10mm, Pitch 0.8mm, IPC Low Density)
pins: 1 P1.5/CEX2 (io), 2 P1.6/SCL (io), 3 P1.7/SDA (io), 4 RST (in), 5 P3.0/RxD (io), 6 NIC, 7 P3.1/TxD (io), 8 P3.2/~{INT}0 (io), 9 P3.3/~{INT}1 (io), 10 P3.4/T0/CEX3 (io), 11 P3.5/T1/CEX4 (io), 12 P3.6/~{WR} (io), 13 P3.7/~{RD} (io), 14 XTAL2 (out), 15 XTAL1 (in), 16 VSS (power), 17 NIC, 18 P2.0/A8 (io), 19 P2.1/A9 (io), 20 P2.2/A10 (io), 21 P2.3/A11 (io), 22 P2.4/A12 (io), 23 P2.5/A13 (io), 24 P2.6/A14 (io), 25 P2.7/A15 (io), 26 ~{PSEN} (out), 27 ALE (out), 28 NIC, 29 ~{EA}/VPP (in), 30 P0.7/AD7 (io), 31 P0.6/AD6 (io), 32 P0.5/AD5 (io), 33 P0.4/AD4 (io), 34 P0.3/AD3 (io), 35 P0.2/AD2 (io), 36 P0.1/AD1 (io), 37 P0.0/AD0 (io), 38 VCC (power), 39 NIC, 40 P1.0/T2 (io), 41 P1.1/T2EX (io), 42 P1.2/ECI (io), 43 P1.3/CEX0 (io), 44 P1.4/CEX1 (io)

## P89C668HBA
designator U?
80C51 8-Bit Flash Microcontroller Family, 64 kB ISP/IAP Flash with 8 kB RAM
footprint SOT187-2_N (Leaded Chip Carrier, 44-Leads, Body 16.6x16.6mm, Pitch 1.27mm, IPC Medium Density)
footprint SOT187-2_L (Leaded Chip Carrier, 44-Leads, Body 16.6x16.6mm, Pitch 1.27mm, IPC High Density)
footprint SOT187-2_M (Leaded Chip Carrier, 44-Leads, Body 16.6x16.6mm, Pitch 1.27mm, IPC Low Density)
pins: 1 NIC, 2 P1.0/T2 (io), 3 P1.1/T2EX (io), 4 P1.2/ECI (io), 5 P1.3/CEX0 (io), 6 P1.4/CEX1 (io), 7 P1.5/CEX2 (io), 8 P1.6/SCL (io), 9 P1.7/SDA (io), 10 RST (in), 11 P3.0/RxD (io), 12 NIC, 13 P3.1/TxD (io), 14 P3.2/~{INT}0 (io), 15 P3.3/~{INT}1 (io), 16 P3.4/T0/CEX3 (io), 17 P3.5/T1/CEX4 (io), 18 P3.6/~{WR} (io), 19 P3.7/~{RD} (io), 20 XTAL2 (out), 21 XTAL1 (in), 22 VSS (power), 23 NIC, 24 P2.0/A8 (io), 25 P2.1/A9 (io), 26 P2.2/A10 (io), 27 P2.3/A11 (io), 28 P2.4/A12 (io), 29 P2.5/A13 (io), 30 P2.6/A14 (io), 31 P2.7/A15 (io), 32 ~{PSEN} (out), 33 ALE (out), 34 NIC, 35 ~{EA}/VPP (in), 36 P0.7/AD7 (io), 37 P0.6/AD6 (io), 38 P0.5/AD5 (io), 39 P0.4/AD4 (io), 40 P0.3/AD3 (io), 41 P0.2/AD2 (io), 42 P0.1/AD1 (io), 43 P0.0/AD0 (io), 44 VCC (power)

## P89C668HBBD
designator U?
80C51 8-Bit Flash Microcontroller Family, 64 kB ISP/IAP Flash with 8 kB RAM
footprint SOT389-1_N (Thin QFP, 44-Leads, Body 10x10mm, Pitch 0.8mm, IPC Medium Density)
footprint SOT389-1_L (Thin QFP, 44-Leads, Body 10x10mm, Pitch 0.8mm, IPC High Density)
footprint SOT389-1_M (Thin QFP, 44-Leads, Body 10x10mm, Pitch 0.8mm, IPC Low Density)
pins: 1 P1.5/CEX2 (io), 2 P1.6/SCL (io), 3 P1.7/SDA (io), 4 RST (in), 5 P3.0/RxD (io), 6 NIC, 7 P3.1/TxD (io), 8 P3.2/~{INT}0 (io), 9 P3.3/~{INT}1 (io), 10 P3.4/T0/CEX3 (io), 11 P3.5/T1/CEX4 (io), 12 P3.6/~{WR} (io), 13 P3.7/~{RD} (io), 14 XTAL2 (out), 15 XTAL1 (in), 16 VSS (power), 17 NIC, 18 P2.0/A8 (io), 19 P2.1/A9 (io), 20 P2.2/A10 (io), 21 P2.3/A11 (io), 22 P2.4/A12 (io), 23 P2.5/A13 (io), 24 P2.6/A14 (io), 25 P2.7/A15 (io), 26 ~{PSEN} (out), 27 ALE (out), 28 NIC, 29 ~{EA}/VPP (in), 30 P0.7/AD7 (io), 31 P0.6/AD6 (io), 32 P0.5/AD5 (io), 33 P0.4/AD4 (io), 34 P0.3/AD3 (io), 35 P0.2/AD2 (io), 36 P0.1/AD1 (io), 37 P0.0/AD0 (io), 38 VCC (power), 39 NIC, 40 P1.0/T2 (io), 41 P1.1/T2EX (io), 42 P1.2/ECI (io), 43 P1.3/CEX0 (io), 44 P1.4/CEX1 (io)

## P89C668HFA
designator U?
80C51 8-Bit Flash Microcontroller Family, 64 kB ISP/IAP Flash with 8 kB RAM
footprint SOT187-2_N (Leaded Chip Carrier, 44-Leads, Body 16.6x16.6mm, Pitch 1.27mm, IPC Medium Density)
footprint SOT187-2_L (Leaded Chip Carrier, 44-Leads, Body 16.6x16.6mm, Pitch 1.27mm, IPC High Density)
footprint SOT187-2_M (Leaded Chip Carrier, 44-Leads, Body 16.6x16.6mm, Pitch 1.27mm, IPC Low Density)
pins: 1 NIC, 2 P1.0/T2 (io), 3 P1.1/T2EX (io), 4 P1.2/ECI (io), 5 P1.3/CEX0 (io), 6 P1.4/CEX1 (io), 7 P1.5/CEX2 (io), 8 P1.6/SCL (io), 9 P1.7/SDA (io), 10 RST (in), 11 P3.0/RxD (io), 12 NIC, 13 P3.1/TxD (io), 14 P3.2/~{INT}0 (io), 15 P3.3/~{INT}1 (io), 16 P3.4/T0/CEX3 (io), 17 P3.5/T1/CEX4 (io), 18 P3.6/~{WR} (io), 19 P3.7/~{RD} (io), 20 XTAL2 (out), 21 XTAL1 (in), 22 VSS (power), 23 NIC, 24 P2.0/A8 (io), 25 P2.1/A9 (io), 26 P2.2/A10 (io), 27 P2.3/A11 (io), 28 P2.4/A12 (io), 29 P2.5/A13 (io), 30 P2.6/A14 (io), 31 P2.7/A15 (io), 32 ~{PSEN} (out), 33 ALE (out), 34 NIC, 35 ~{EA}/VPP (in), 36 P0.7/AD7 (io), 37 P0.6/AD6 (io), 38 P0.5/AD5 (io), 39 P0.4/AD4 (io), 40 P0.3/AD3 (io), 41 P0.2/AD2 (io), 42 P0.1/AD1 (io), 43 P0.0/AD0 (io), 44 VCC (power)

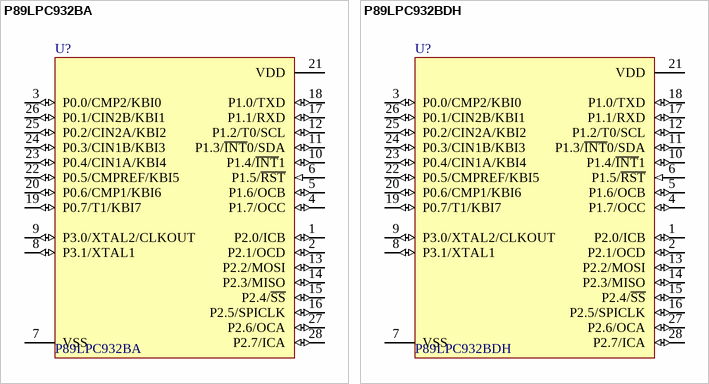
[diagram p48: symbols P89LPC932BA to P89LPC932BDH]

## P89LPC932BA
designator U?
80C51 8-Bit Microcontroller with Two-Clock Core, 8 kB 3 V Low-Power Flash with 512 B Data EEPROM
footprint SOT261-2_N (Leaded Chip Carrier, 28-Leads, Body 11.5x11.5mm, Pitch 1.27mm, IPC Medium Density)
footprint SOT261-2_L (Leaded Chip Carrier, 28-Leads, Body 11.5x11.5mm, Pitch 1.27mm, IPC High Density)
footprint SOT261-2_M (Leaded Chip Carrier, 28-Leads, Body 11.5x11.5mm, Pitch 1.27mm, IPC Low Density)
pins: 1 P2.0/ICB (io), 2 P2.1/OCD (io), 3 P0.0/CMP2/KBI0 (io), 4 P1.7/OCC (io), 5 P1.6/OCB (io), 6 P1.5/~{RST} (in), 7 VSS (power), 8 P3.1/XTAL1 (io), 9 P3.0/XTAL2/CLKOUT (io), 10 P1.4/~{INT}1 (io), 11 P1.3/~{INT}0/SDA (io), 12 P1.2/T0/SCL (io), 13 P2.2/MOSI (io), 14 P2.3/MISO (io), 15 P2.4/~{SS} (io), 16 P2.5/SPICLK (io), 17 P1.1/RXD (io), 18 P1.0/TXD (io), 19 P0.7/T1/KBI7 (io), 20 P0.6/CMP1/KBI6 (io), 21 VDD (power), 22 P0.5/CMPREF/KBI5 (io), 23 P0.4/CIN1A/KBI4 (io), 24 P0.3/CIN1B/KBI3 (io), 25 P0.2/CIN2A/KBI2 (io), 26 P0.1/CIN2B/KBI1 (io), 27 P2.6/OCA (io), 28 P2.7/ICA (io)

## P89LPC932BDH
designator U?
80C51 8-Bit Microcontroller with Two-Clock Core, 8 kB 3 V Low-Power Flash with 512 B Data EEPROM
footprint SOT361-1 (Shrink Small Outline; 28 Leads; Body Width 4.4 mm; Pitch 0.65 mm)
pins: 1 P2.0/ICB (io), 2 P2.1/OCD (io), 3 P0.0/CMP2/KBI0 (io), 4 P1.7/OCC (io), 5 P1.6/OCB (io), 6 P1.5/~{RST} (in), 7 VSS (power), 8 P3.1/XTAL1 (io), 9 P3.0/XTAL2/CLKOUT (io), 10 P1.4/~{INT}1 (io), 11 P1.3/~{INT}0/SDA (io), 12 P1.2/T0/SCL (io), 13 P2.2/MOSI (io), 14 P2.3/MISO (io), 15 P2.4/~{SS} (io), 16 P2.5/SPICLK (io), 17 P1.1/RXD (io), 18 P1.0/TXD (io), 19 P0.7/T1/KBI7 (io), 20 P0.6/CMP1/KBI6 (io), 21 VDD (power), 22 P0.5/CMPREF/KBI5 (io), 23 P0.4/CIN1A/KBI4 (io), 24 P0.3/CIN1B/KBI3 (io), 25 P0.2/CIN2A/KBI2 (io), 26 P0.1/CIN2B/KBI1 (io), 27 P2.6/OCA (io), 28 P2.7/ICA (io)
